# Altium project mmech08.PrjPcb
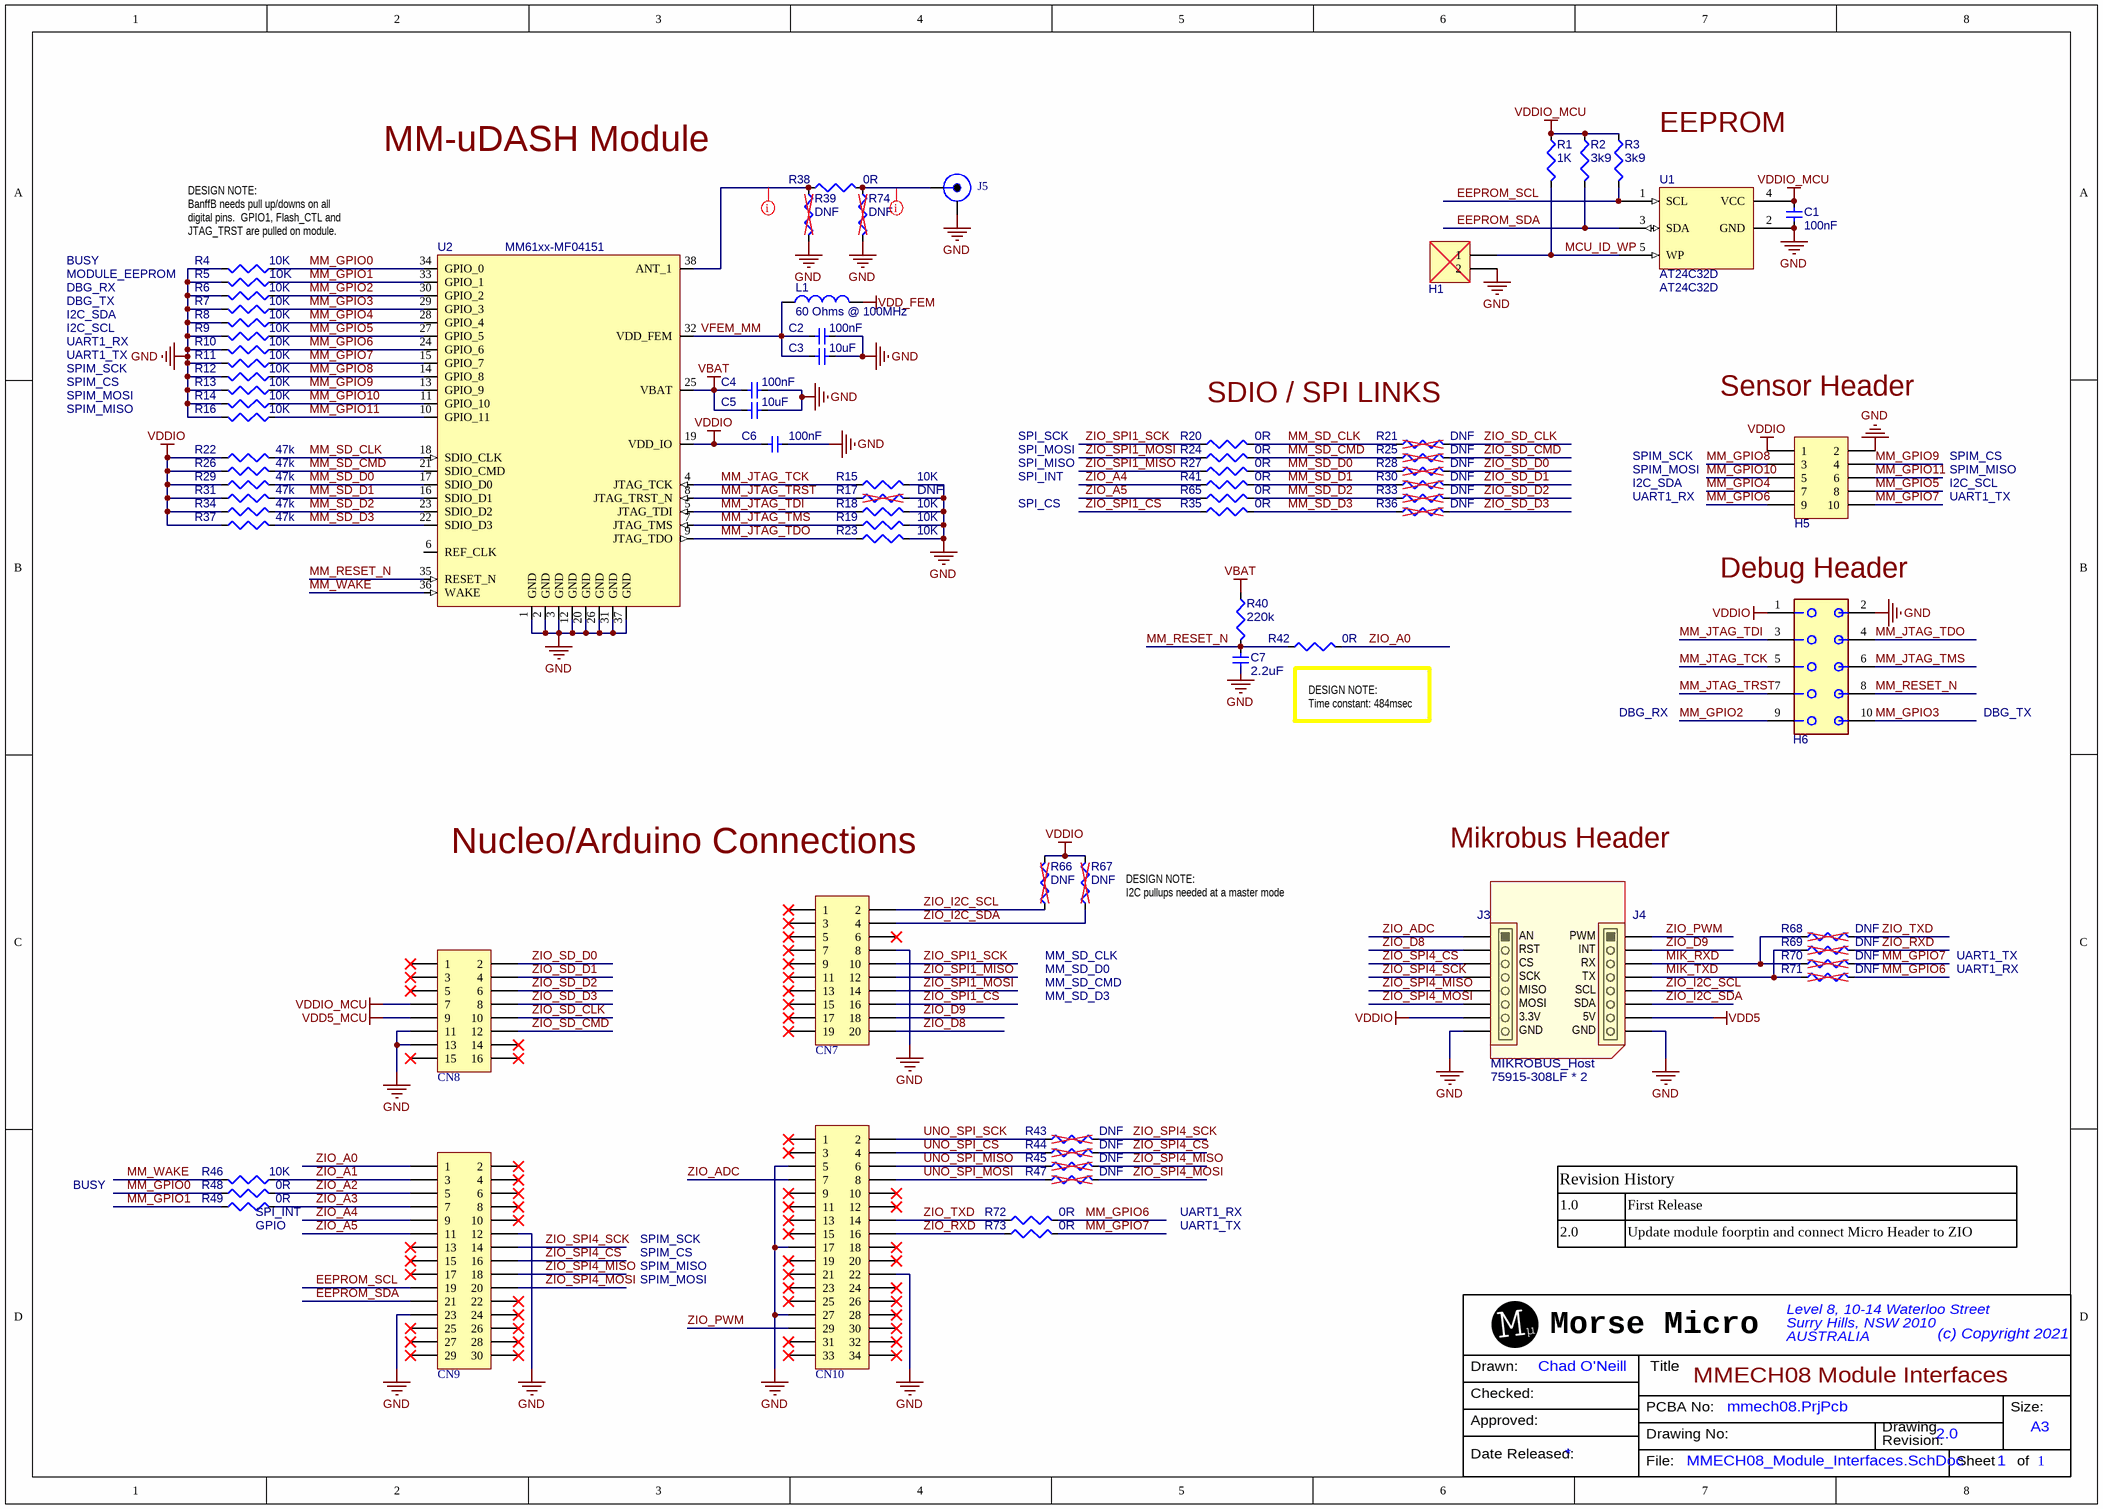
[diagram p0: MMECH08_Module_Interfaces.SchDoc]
Project: MM_EVC3; Revision: 1
2 sheets, 121 parts. Net scope: global (net labels, ports and power ports of the same name join across sheets).
Board file: mmech08.PcbDoc
Sheets:
  MMECH08_Module_Interfaces.SchDoc
  MMECH08_Power.SchDoc

## Sheet MMECH08_Module_Interfaces.SchDoc: MMECH08 Module Interfaces
size A3; Organization: Morse Micro; Revision: 2.0; SheetNumber: 1; SheetTotal: 1; DrawnBy: Chad O'Neill; Engineer: Insu Moon

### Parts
C1  value 100nF  [0402_cap]  (hidden comment: CAP)
C2  value 100nF  [0402_cap]  (hidden comment: CAP)
C3  value 10uF  [0402_cap]  (hidden comment: CAP)
C4  value 100nF  [0402_cap]  (hidden comment: CAP)
C5  value 10uF  [0402_cap]  (hidden comment: CAP)
C6  value 100nF  [0402_cap]  (hidden comment: CAP)
C7  value 2.2uF  [0402_cap]  (hidden comment: CAP)
CN7  .Designator  [HDR2X10]  (value not drawn)
CN8  .Designator  [HDR2X8]  (value not drawn)
CN9  .Designator  [HDR2X15]  (value not drawn)
CN10  .Designator  [HDR2X17]  (value not drawn)
H1  HDR_1X2_DNF  [HDR1X2_DNF]  (value not drawn)  (no BOM)
H5  HDR_2X5  [HDR2X5]  (value not drawn)
H6  2X5_FTSH_DV_K  [FTSH_105_D_K]  (value not drawn)
J3  75915-308LF * 2  [75915-308LF]
J4  75915-308LF  [75915-308LF]  (value not drawn)
J5  SMA-EDGE  [SMA_RA-Edge]  (value not drawn)
L1  value 60 Ohms @ 100MHz  [0402_ind]  (hidden comment: IND)
R1  value 1K  [0402_res]  (hidden comment: RES)
R2  value 3k9  [0402_res]  (hidden comment: RES)
R3  value 3k9  [0402_res]  (hidden comment: RES)
R4  value 10K  [0402_res]  (hidden comment: RES)
R5  value 10K  [0402_res]  (hidden comment: RES)
R6  value 10K  [0402_res]  (hidden comment: RES)
R7  value 10K  [0402_res]  (hidden comment: RES)
R8  value 10K  [0402_res]  (hidden comment: RES)
R9  value 10K  [0402_res]  (hidden comment: RES)
R10  value 10K  [0402_res]  (hidden comment: RES)
R11  value 10K  [0402_res]  (hidden comment: RES)
R12  value 10K  [0402_res]  (hidden comment: RES)
R13  value 10K  [0402_res]  (hidden comment: RES)
R14  value 10K  [0402_res]  (hidden comment: RES)
R15  value 10K  [0402_res]  (hidden comment: RES)
R16  value 10K  [0402_res]  (hidden comment: RES)
R17  value DNF  [0402_res_dnf]  (hidden comment: RES_DNF)  (no BOM)
R18  value 10K  [0402_res]  (hidden comment: RES)
R19  value 10K  [0402_res]  (hidden comment: RES)
R20  value 0R  [0603_res]  (hidden comment: RES)
R21  value DNF  [0603_res_dnf]  (hidden comment: RES_DNF)  (no BOM)
R22  value 47k  [0402_res]  (hidden comment: RES)
R23  value 10K  [0402_res]  (hidden comment: RES)
R24  value 0R  [0603_res]  (hidden comment: RES)
R25  value DNF  [0603_res_dnf]  (hidden comment: RES_DNF)  (no BOM)
R26  value 47k  [0402_res]  (hidden comment: RES)
R27  value 0R  [0603_res]  (hidden comment: RES)
R28  value DNF  [0603_res_dnf]  (hidden comment: RES_DNF)  (no BOM)
R29  value 47k  [0402_res]  (hidden comment: RES)
R30  value DNF  [0603_res_dnf]  (hidden comment: RES_DNF)  (no BOM)
R31  value 47k  [0402_res]  (hidden comment: RES)
R33  value DNF  [0603_res_dnf]  (hidden comment: RES_DNF)  (no BOM)
R34  value 47k  [0402_res]  (hidden comment: RES)
R35  value 0R  [0603_res]  (hidden comment: RES)
R36  value DNF  [0603_res_dnf]  (hidden comment: RES_DNF)  (no BOM)
R37  value 47k  [0402_res]  (hidden comment: RES)
R38  value 0R  [0402_res]  (hidden comment: RES)
R39  value DNF  [0402_res_dnf]  (hidden comment: RES_DNF)  (no BOM)
R40  value 220k  [0402_res]  (hidden comment: RES)
R41  value 0R  [0603_res]  (hidden comment: RES)
R42  value 0R  [0402_res]  (hidden comment: RES)
R43  value DNF  [0603_res_dnf]  (hidden comment: RES_DNF)  (no BOM)
R44  value DNF  [0603_res_dnf]  (hidden comment: RES_DNF)  (no BOM)
R45  value DNF  [0603_res_dnf]  (hidden comment: RES_DNF)  (no BOM)
R46  value 10K  [0402_res]  (hidden comment: RES)
R47  value DNF  [0603_res_dnf]  (hidden comment: RES_DNF)  (no BOM)
R48  value 0R  [0402_res]  (hidden comment: RES)
R49  value 0R  [0402_res]  (hidden comment: RES)
R65  value 0R  [0603_res]  (hidden comment: RES)
R66  value DNF  [0603_res_dnf]  (hidden comment: RES_DNF)  (no BOM)
R67  value DNF  [0603_res_dnf]  (hidden comment: RES_DNF)  (no BOM)
R68  value DNF  [0603_res_dnf]  (hidden comment: RES_DNF)  (no BOM)
R69  value DNF  [0603_res_dnf]  (hidden comment: RES_DNF)  (no BOM)
R70  value DNF  [0603_res_dnf]  (hidden comment: RES_DNF)  (no BOM)
R71  value DNF  [0603_res_dnf]  (hidden comment: RES_DNF)  (no BOM)
R72  value 0R  [0603_res]  (hidden comment: RES)
R73  value 0R  [0603_res]  (hidden comment: RES)
R74  value DNF  [0402_res_dnf]  (hidden comment: RES_DNF)  (no BOM)
U1  AT24C32D  [SOT-23_5]
U2  MM61xx-MF04151  [MF04]
U3  MIKROBUS_Host  [MIKROBUS_Host_SD]

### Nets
GND: C1.2 C2.2 C3.2 C4.1 C5.2 C6.2 C7.2 CN7.8 CN8.11 CN8.13 CN9.12 CN9.23 CN10.5 CN10.17 CN10.22 CN10.27 H1.2 H5.2 H6.2 J3.8 J4.8 J5.2 R4.2 R5.2 R6.2 R7.2 R8.2 R9.2 R10.2 R11.2 R12.2 R13.2 R14.2 R15.2 R16.2 R17.2 R18.2 R19.2 R23.2 R39.2 R74.2 U1.2(GND) U2.1(GND) U2.2(GND) U2.3(GND) U2.12(GND) U2.20(GND) U2.26(GND) U2.31(GND) U2.37(GND)
VBAT: C4.2 C5.1 R40.1 U2.25(VBAT)
VDD5: J4.7
VDD5_MCU: CN8.9
VDD_FEM: L1.2
VDDIO: C6.1 H5.1 H6.1 J3.7 R22.1 R26.1 R29.2 R31.2 R34.2 R37.1 R66.1 R67.1 U2.19(VDD_IO)
VDDIO_MCU: C1.1 CN8.7 R1.1 R2.1 R3.1 U1.4(VCC)
EEPROM_SCL: CN9.19 R3.2 U1.1(SCL)
EEPROM_SDA: CN9.21 R2.2 U1.3(SDA)
MCU_ID_WP: H1.1 R1.2 U1.5(WP)
MIK_RXD: J4.3 R68.1 R70.1
MIK_TXD: J4.4 R69.1 R71.1
MM_GPIO0: R4.1 R48.1 U2.34(GPIO_0)
MM_GPIO1: R5.1 R49.1 U2.33(GPIO_1)
MM_GPIO2: H6.9 R6.1 U2.30(GPIO_2)
MM_GPIO3: H6.10 R7.1 U2.29(GPIO_3)
MM_GPIO4: H5.7 R8.1 U2.28(GPIO_4)
MM_GPIO5: H5.8 R9.1 U2.27(GPIO_5)
MM_GPIO6: H5.9 R10.1 R71.2 R72.2 U2.24(GPIO_6)
MM_GPIO7: H5.10 R11.1 R70.2 R73.2 U2.15(GPIO_7)
MM_GPIO8: H5.3 R12.1 U2.14(GPIO_8)
MM_GPIO9: H5.4 R13.1 U2.13(GPIO_9)
MM_GPIO10: H5.5 R14.1 U2.11(GPIO_10)
MM_GPIO11: H5.6 R16.1 U2.10(GPIO_11)
MM_JTAG_TCK: H6.5 R15.1 U2.4(JTAG_TCK)
MM_JTAG_TDI: H6.3 R18.1 U2.5(JTAG_TDI)
MM_JTAG_TDO: H6.4 R23.1 U2.9(JTAG_TDO)
MM_JTAG_TMS: H6.6 R19.1 U2.7(JTAG_TMS)
MM_JTAG_TRST: H6.7 R17.1 U2.8(JTAG_TRST_N)
MM_RESET_N: C7.1 H6.8 R40.2 R42.1 U2.35(RESET_N)
MM_SD_CLK: R20.2 R21.1 R22.2 U2.18(SDIO_CLK)
MM_SD_CMD: R24.2 R25.1 R26.2 U2.21(SDIO_CMD)
MM_SD_D0: R27.2 R28.1 R29.1 U2.17(SDIO_D0)
MM_SD_D1: R30.1 R31.1 R41.2 U2.16(SDIO_D1)
MM_SD_D2: R33.1 R34.1 R65.2 U2.23(SDIO_D2)
MM_SD_D3: R35.2 R36.1 R37.2 U2.22(SDIO_D3)
MM_WAKE: R46.1 U2.36(WAKE)
UNO_SPI_CS: CN10.4 R44.1
UNO_SPI_MISO: CN10.6 R45.1
UNO_SPI_MOSI: CN10.8 R47.1
UNO_SPI_SCK: CN10.2 R43.1
VFEM_MM: C2.1 C3.1 L1.1 U2.32(VDD_FEM)
ZIO_A0: CN9.1 R42.2
ZIO_A1: CN9.3 R46.2
ZIO_A2: CN9.5 R48.2
ZIO_A3: CN9.7 R49.2
ZIO_A4: CN9.9 R41.1
ZIO_A5: CN9.11 R65.1
ZIO_ADC: CN10.7 J3.1
ZIO_D8: CN7.20 J3.2
ZIO_D9: CN7.18 J4.2
ZIO_I2C_SCL: CN7.2 J4.5 R66.2
ZIO_I2C_SDA: CN7.4 J4.6 R67.2
ZIO_PWM: CN10.29 J4.1
ZIO_RXD: CN10.16 R69.2 R73.1
ZIO_SD_CLK: CN8.10 R21.2
ZIO_SD_CMD: CN8.12 R25.2
ZIO_SD_D0: CN8.2 R28.2
ZIO_SD_D1: CN8.4 R30.2
ZIO_SD_D2: CN8.6 R33.2
ZIO_SD_D3: CN8.8 R36.2
ZIO_SPI1_CS: CN7.16 R35.1
ZIO_SPI1_MISO: CN7.12 R27.1
ZIO_SPI1_MOSI: CN7.14 R24.1
ZIO_SPI1_SCK: CN7.10 R20.1
ZIO_SPI4_CS: CN9.16 J3.3 R44.2
ZIO_SPI4_MISO: CN9.18 J3.5 R45.2
ZIO_SPI4_MOSI: CN9.20 J3.6 R47.2
ZIO_SPI4_SCK: CN9.14 J3.4 R43.2
ZIO_TXD: CN10.14 R68.2 R72.1
NetJ5_1: J5.1 R38.2 R74.1
NetR38_1: R38.1 R39.1 U2.38(ANT_1)

Not connected (* = marked no-connect by the designer): CN7 1* 3* 5* 6* 7* 9* 11* 13* 15* 17* 19*; CN8 1* 3* 5* 14* 15* 16*; CN9 2* 4* 6* 8* 10* 13* 15* 17* 22* 24* 25* 26* 27* 28* 29* 30*; CN10 1* 3* 9* 10* 11* 12* 13* 15* 18* 19* 20* 21* 23* 24* 25* 26* 28* 30* 31* 32* 33* 34*; U2 6(REF_CLK)

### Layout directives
net class RF-Net: NetJ5_1, NetR38_1

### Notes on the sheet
- MM-uDASH Module
- EEPROM
- DESIGN NOTE:
  BanffB needs pull up/downs on all digital pins.  GPIO1, Flash_CTL and JTAG_TRST are pulled on module.
- DBG_RX
- DBG_TX
- BUSY
- I2C_SDA
- MODULE_EEPROM
- SPIM_SCK
- I2C_SCL
- UART1_RX
- UART1_TX
- SPIM_CS
- SPIM_MOSI
- SPIM_MISO
- SPI_MOSI
- SPI_SCK
- SDIO / SPI LINKS
- (near H5) Sensor Header
- SPI_MISO
- SPI_CS
- SPI_INT
- (near H6) Debug Header
- (near R42) DESIGN NOTE:
  Time constant: 484msec
- (near CN7) Nucleo/Arduino Connections
- Mikrobus Header
- (near R67) DESIGN NOTE:
  I2C pullups needed at a master mode
- MM_SD_CLK
- MM_SD_D0
- MM_SD_CMD
- MM_SD_D3
- Revision History
- (near R49) SPI_INT
- (near R49) GPIO
- 1.0
- 2.0
- First Release
- Update module foorptin and connect Micro Header to ZIO

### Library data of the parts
C1 C2 C4 C6 = CAP0084: Cap,100nF,10V,+/-10%,X7R,0402; Manufacturer 1: Kemet; Manufacturer Part Number 1: C0402C104K8RACTU; Generic Allowed: Yes; Subtype: Ceramic; Tolerance: 10%
C3 C5 = CAP0014: CAP CER 10UF 10V 20% X5R 0402; Manufacturer 1: Samsung; Manufacturer Part Number 1: CL05A106MP8NUB8; Generic Allowed: Yes; Subtype: Ceramic
C7 = CAP0023: CAP CER 2.2UF 25V 20% X5R 0402; Manufacturer 1: Murata; Manufacturer Part Number 1: GRM155R61E225ME15D; Generic Allowed: Yes; Subtype: Ceramic
CN7 = HDR0019: Conn Straight Header 10x2 0.100" 20 POS; Manufacturer 1: Molex/Waldom Electronics Corp; Manufacturer Part Number 1: 90131-0130; Generic Allowed: Yes
CN8 = HDR0015: Conn Straight Header 8x2 0.100" 16 POS; Manufacturer 1: Molex/Waldom Electronics Corp; Manufacturer Part Number 1: 90131-0128; Generic Allowed: Yes
CN9 = HDR0027: Conn Straight Header 15x2 0.100" 30 POS; Manufacturer 1: Molex/Waldom Electronics Corp; Manufacturer Part Number 1: 90131-0135; Generic Allowed: Yes
CN10 = HDR0029: Conn Straight Header 17x2 0.100" 32 POS; Manufacturer 1: Molex/Waldom Electronics Corp; Manufacturer Part Number 1: 90131-0137; Generic Allowed: Yes
H1 = HDR0098: Conn Straight Header 2x1 0.100" 2 POS (DNF)
H5 = HDR0012: Conn Straight Header 5x2 0.100" 10 POS; Manufacturer 1: Molex/Waldom Electronics Corp; Manufacturer Part Number 1: 90131-0125; Generic Allowed: Yes
H6 = HDR0090: CONN,Vertical FTSH Series,0.05"10 Pins, Through Hole; Manufacturer 1: Samtec; Manufacturer Part Number 1: FTSH-105-01-F-D-K; Generic Allowed: No
J3 J4 = CON0063: CONN RCPT 8POS 0.1 GOLD PCB; Manufacturer 1: Amphenol FCI; Generic Allowed: No
J5 = CON0004: Conn SMA Right Angel .187" Female Socket; Manufacturer 1: Emerson Network; Manufacturer Part Number 1: 142-0701-801; Rule: UNIONINDEX{}0[]RULEKIND{}PolygonConnect[]NETSCOPE{}DifferentNets[]LAYERKIND{}SameLayer[]NAME{}Schematic Polygon Connect Style[]CONNECTSTYLE{}Direct[]RELIEFCONDUCTORWIDTH{}10mil[]RELIEFENTRIES{}4[]POLYGONRELIEFANGLE{}45 Angle[]UNIT{}Imperial[]PcbType{}ProtelPcb; Generic Allowed: No
L1 = IND0083: BEAD 60OHMS 2500MA 32 MOHM; Manufacturer 1: Murata; Manufacturer Part Number 1: BLM15PX600SN1D; Current: 2.5A; Generic Allowed: Yes; Resistance: 32mOhm
R1 = RES0004: RES SMD 1Kohm 1% 1/10W Thick film 0402; Manufacturer 1: Panasonic; Manufacturer Part Number 1: ERJ-2RKF1001X; Generic Allowed: Yes
R2 R3 = RES0204: RES SMD 3.9K OHM 1% 1/16W 0402; Manufacturer 1: Yageo; Manufacturer Part Number 1: RC0402FR-073K9L; Generic Allowed: Yes
R4-R16 R18 R19 R23 R46 = RES0002: RES SMD 10Kohm 1% 1/10W Thick film 0402; Manufacturer 1: Panasonic; Manufacturer Part Number 1: ERJ-2RKF1002X; Generic Allowed: Yes
R17 R39 R74 = RES0034: Update Later
R20 R24 R27 R35 R41 R65 R72 R73 = RES0119: Res, 0 Ohm, 1/10W,+/-5%,0603 RoHS; Manufacturer 1: Rohm; Manufacturer Part Number 1: MCR03EZPJ000; Tolerance: 5%; Generic Allowed: Yes
R21 R25 R28 R30 R33 R36 R43-R45 R47 R66-R71 = RES0035: Update Later
R22 R26 R29 R31 R34 R37 = RES0086: Res, 47K Ohms,1/16W, 1%, 0402,SMD RoHS; Manufacturer 1: Rohm; Manufacturer Part Number 1: MCR01MZPF4702; Generic Allowed: Yes
R38 R42 R48 R49 = RES0001: RES SMD 0ohm 1% 1/10W Thick film 0402; Manufacturer 1: Panasonic; Manufacturer Part Number 1: ERJ-2GE0R00X; Generic Allowed: Yes
R40 = RES0064: Res, 220k Ohms, 1/16W, 1%, 0402,SMD; Manufacturer 1: Rohm; Manufacturer Part Number 1: MCR01MZPF2203; Generic Allowed: Yes
U1 = ICT0181: IC EEPROM 32KBIT I2C SOT23-5; Manufacturer 1: Microchip Technology; Manufacturer Part Number 1: AT24C32D-STUM-T; Generic Allowed: No
U2 = MOD0007: MM61xx-MF04; Manufacturer 1: Morse Micro
U3 = MOD0012: MIKROBUS Module; Manufacturer Part Number 1: MIKROBUS HOST; Value: MIKROBUS Host

## Sheet MMECH08_Power.SchDoc: MMECH08 Power & Reset
size A3; CompanyName: Morse Micro; DrawnBy: Insu Moon; Engineer: Insu Moon; Revision: 1.0; SheetNumber: 2; SheetTotal: 2; pageName: Regulators; DrawingNumber: 1; PageSetup: Record=PageOptions¦CenterHorizontal=True¦CenterVertical=True¦PrintScale=1.04¦XCorrection=1.00¦YCorrection=1.00¦PrintKind=0¦BorderSize=5000000¦LeftOffset=0¦BottomOffset=0¦Orientation=2¦PaperLength=1000¦PaperWidth=1000¦Scale=100¦PaperSource=7¦PrintQuality=-4¦MediaType=1¦DitherType=10¦PaperKind=A3¦PrintScaleMode=1
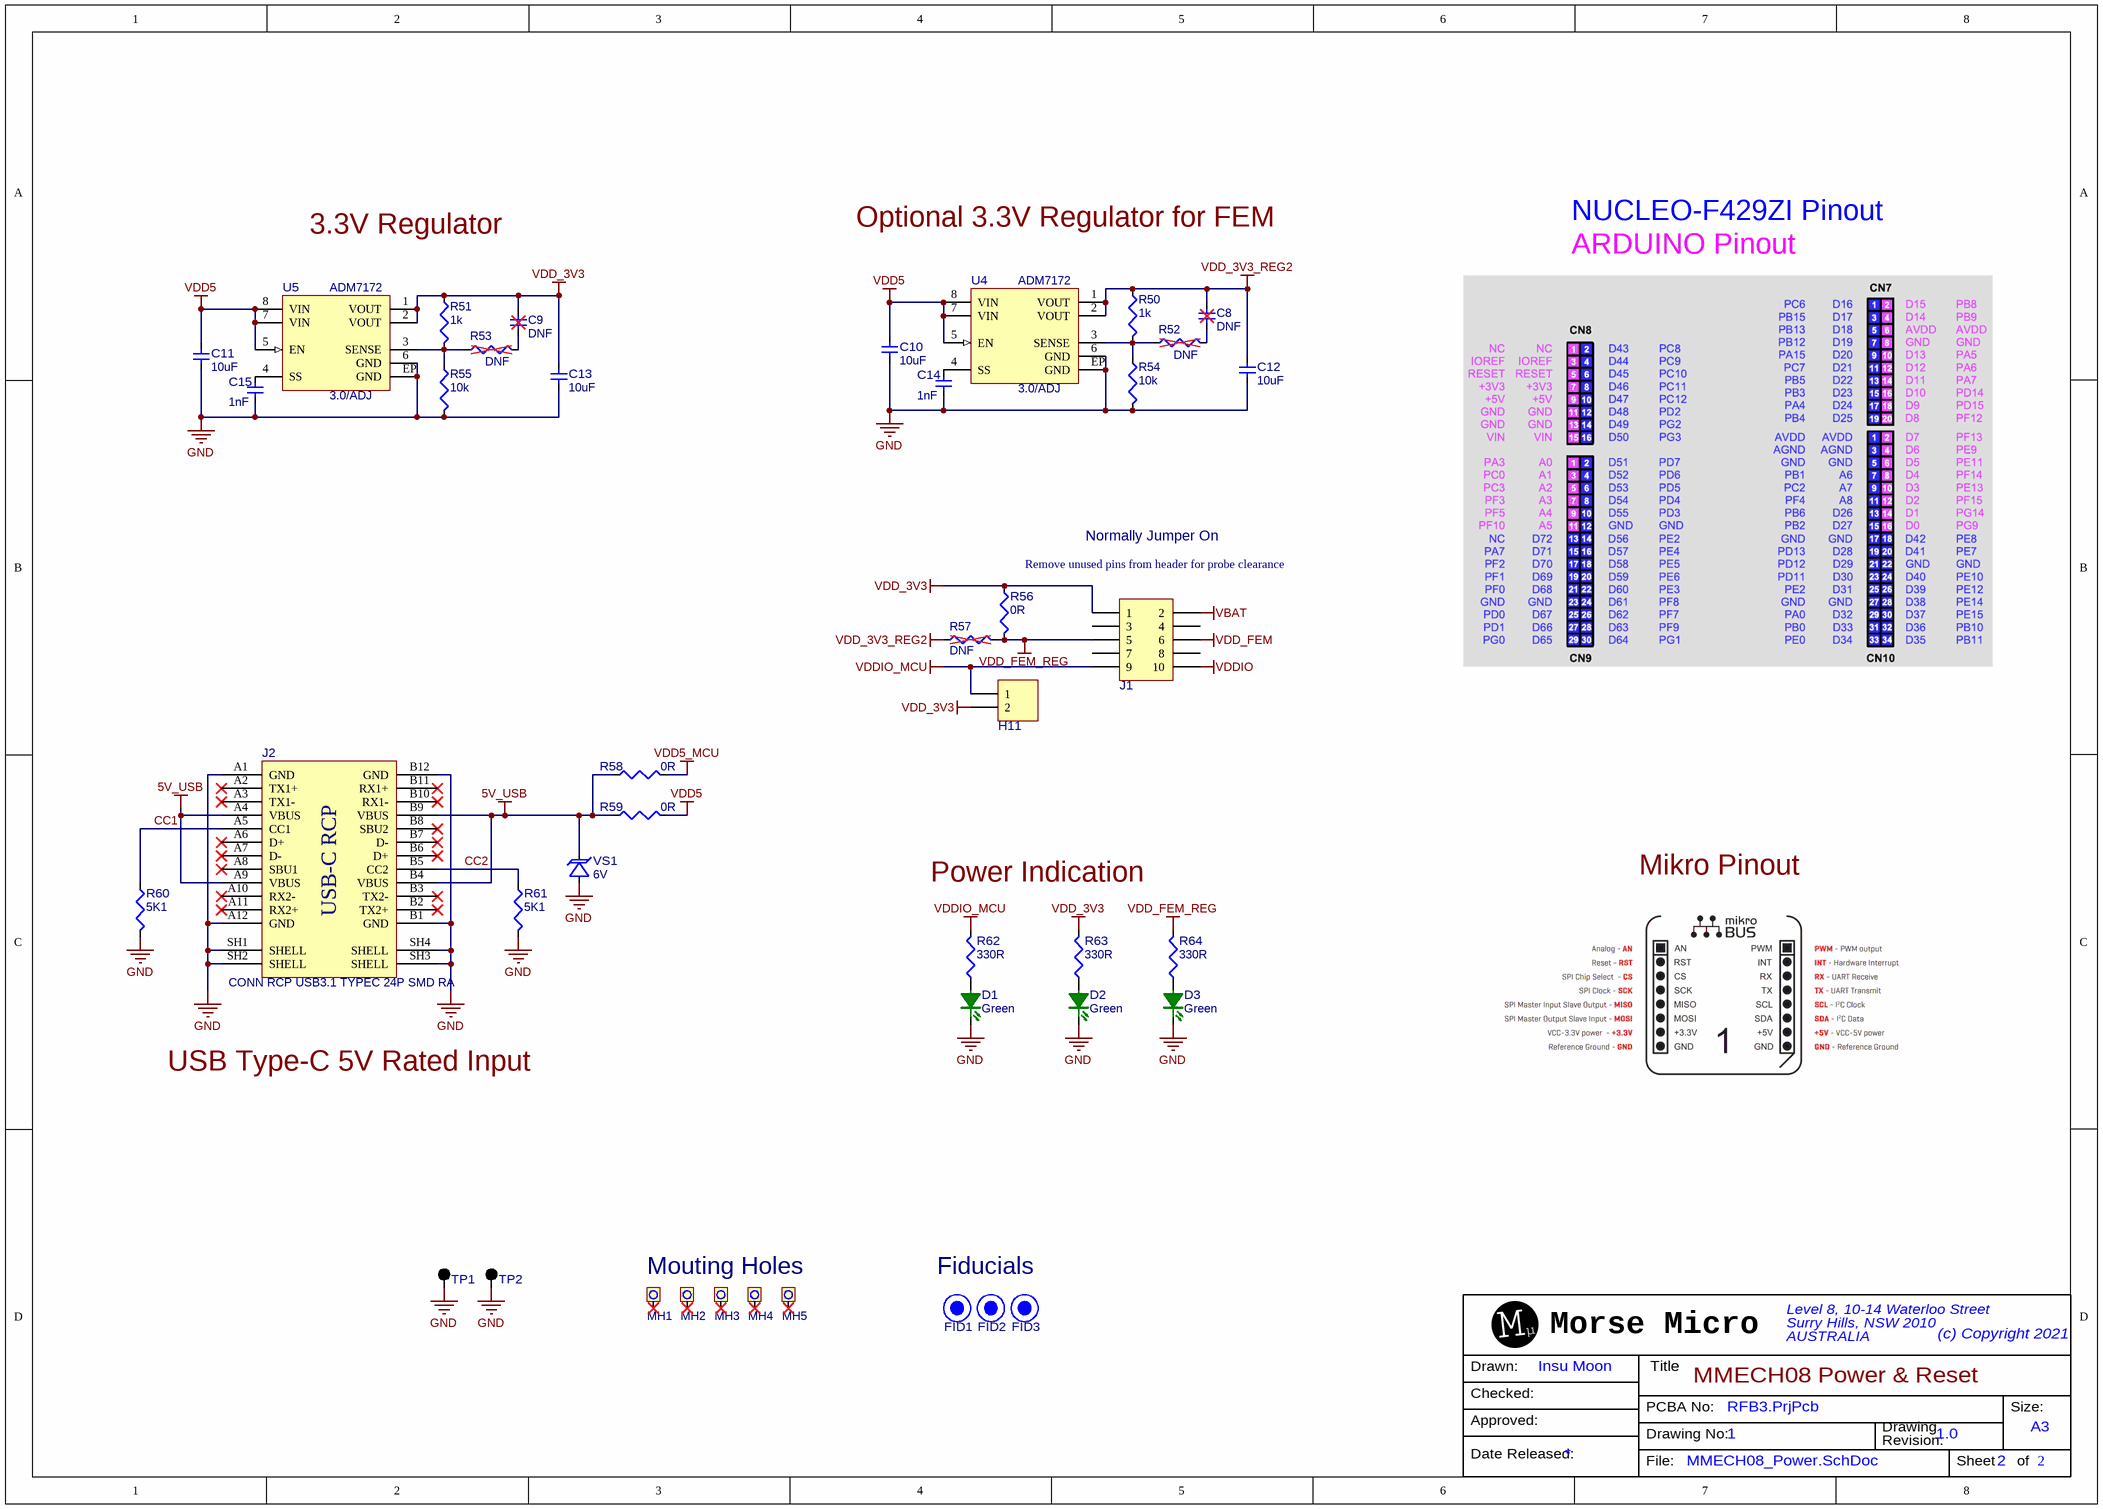
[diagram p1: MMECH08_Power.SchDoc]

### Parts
C8  value DNF  [0402_cap_dnf]  (hidden comment: CAP_DNF)  (no BOM)
C9  value DNF  [0402_cap_dnf]  (hidden comment: CAP_DNF)  (no BOM)
C10  value 10uF  [0603_cap]  (hidden comment: CAP)
C11  value 10uF  [0603_cap]  (hidden comment: CAP)
C12  value 10uF  [0603_cap]  (hidden comment: CAP)
C13  value 10uF  [0603_cap]  (hidden comment: CAP)
C14  value 1nF  [0402_cap]  (hidden comment: CAP)
C15  value 1nF  [0402_cap]  (hidden comment: CAP)
D1  value Green  [LED_0402_GREEN]  (hidden comment: LED_G)
D2  value Green  [LED_0402_GREEN]  (hidden comment: LED_G)
D3  value Green  [LED_0402_GREEN]  (hidden comment: LED_G)
FID1  FIDUCIAL  [FIDUCIAL_1MM]  (value not drawn)  (no BOM)
FID2  FIDUCIAL  [FIDUCIAL_1MM]  (value not drawn)  (no BOM)
FID3  FIDUCIAL  [FIDUCIAL_1MM]  (value not drawn)  (no BOM)
H11  HDR_1X2  [HDR1X2]  (value not drawn)
J1  HDR_2X5  [HDR2X5]  (value not drawn)
J2  CONN RCP USB3.1 TYPEC 24P SMD RA  [USB-C_RCP]
MH1  MH_360_320_NPTH  [MH_360_320_NPTH]  (value not drawn)
MH2  MH_360_320_NPTH  [MH_360_320_NPTH]  (value not drawn)
MH3  MH_360_320_NPTH  [MH_360_320_NPTH]  (value not drawn)
MH4  MH_360_320_NPTH  [MH_360_320_NPTH]  (value not drawn)
MH5  MH_360_320_NPTH  [MH_360_320_NPTH]  (value not drawn)
R50  value 1k  [0402_res]  (hidden comment: RES)
R51  value 1k  [0402_res]  (hidden comment: RES)
R52  value DNF  [0402_res_dnf]  (hidden comment: RES_DNF)  (no BOM)
R53  value DNF  [0402_res_dnf]  (hidden comment: RES_DNF)  (no BOM)
R54  value 10k  [0402_res]  (hidden comment: RES)
R55  value 10k  [0402_res]  (hidden comment: RES)
R56  value 0R  [0603_res]  (hidden comment: RES)
R57  value DNF  [0603_res_dnf]  (hidden comment: RES_DNF)  (no BOM)
R58  value 0R  [0603_res]  (hidden comment: RES)
R59  value 0R  [0603_res]  (hidden comment: RES)
R60  value 5K1  [0402_res]  (hidden comment: RES)
R61  value 5K1  [0402_res]  (hidden comment: RES)
R62  value 330R  [0402_res]  (hidden comment: RES)
R63  value 330R  [0402_res]  (hidden comment: RES)
R64  value 330R  [0402_res]  (hidden comment: RES)
TP1  TP-BLK  [TP-100_BLACK]  (value not drawn)
TP2  TP-BLK  [TP-100_BLACK]  (value not drawn)
U4  Voltage: 3.0/ADJ  [PSON50P300X80_HS-9N]  (hidden comment: ADM7172)
U5  Voltage: 3.0/ADJ  [PSON50P300X80_HS-9N]  (hidden comment: ADM7172)
VS1  value 6V  [DO-214AC]  (hidden comment: Varistor_Uni)

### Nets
5V_USB: J2.A4(VBUS) J2.A9(VBUS) J2.B4(VBUS) J2.B9(VBUS) R58.1 R59.1 VS1.K
GND: C10.2 C11.2 C12.2 C13.2 C14.2 C15.2 D1.K D2.K D3.K J2.A1(GND) J2.A12(GND) J2.B1(GND) J2.B12(GND) J2.SH1(SHELL) J2.SH2(SHELL) J2.SH3(SHELL) J2.SH4(SHELL) R54.2 R55.2 R60.2 R61.2 TP1.1 TP2.1 U4.6(GND) U4.EP(GND) U5.6(GND) U5.EP(GND) VS1.A
VBAT: J1.2
VDD5: C10.1 C11.1 R59.2 U4.5(EN) U4.7(VIN) U4.8(VIN) U5.5(EN) U5.7(VIN) U5.8(VIN)
VDD5_MCU: R58.2
VDD_3V3: C9.1 C13.1 H11.2 J1.1 R51.1 R56.1 R63.2 U5.1(VOUT) U5.2(VOUT)
VDD_3V3_REG2: C8.1 C12.1 R50.1 R57.1 U4.1(VOUT) U4.2(VOUT)
VDD_FEM: J1.6
VDD_FEM_REG: J1.5 R56.2 R57.2 R64.2
VDDIO: J1.10
VDDIO_MCU: H11.1 J1.9 R62.2
CC1: J2.A5(CC1) R60.1
CC2: J2.B5(CC2) R61.1
NetC8_2: C8.2 R52.2
NetC9_2: C9.2 R53.2
NetC14_1: C14.1 U4.4(SS)
NetC15_1: C15.1 U5.4(SS)
NetD1_A: D1.A R62.1
NetD2_A: D2.A R63.1
NetD3_A: D3.A R64.1
NetR50_2: R50.2 R52.1 R54.1 U4.3(SENSE)
NetR51_2: R51.2 R53.1 R55.1 U5.3(SENSE)

Not connected (* = marked no-connect by the designer): J1 3 4 7 8; J2 A2(TX1+)* A3(TX1-)* A6(D+)* A7(D-)* A8(SBU1)* A10(RX2-)* A11(RX2+)* B2(TX2+)* B3(TX2-)* B6(D+)* B7(D-)* B8(SBU2)* B10(RX1-)* B11(RX1+)*; MH1 1*; MH2 1*; MH3 1*; MH4 1*; MH5 1*

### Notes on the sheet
- 3.3V Regulator
- Optional 3.3V Regulator for FEM
- NUCLEO-F429ZI Pinout
- ARDUINO Pinout
- Remove unused pins from header for probe clearance
- Normally Jumper On
- Power Indication
- Mikro Pinout
- USB Type-C 5V Rated Input
- Mouting Holes
- Fiducials

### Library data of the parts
C8 C9 = CAP0049: Update Later
C10-C13 = CAP0164: CAP CER 10UF 25V 20% X5R 0603; Manufacturer 1: Murata, Inc.; Manufacturer Part Number 1: GRM188R61E106MA73J; Generic Allowed: Yes; Subtype: Ceramic
C14 C15 = CAP0078: Cap,1nF,50V,+/-10%,X7R,0402, RoHS; Manufacturer 1: Murata, Inc.; Manufacturer Part Number 1: GRM155R71H102KA01D; Generic Allowed: Yes; Subtype: Ceramic; Tolerance: 10%
D1-D3 = DIO0046: LED GREEN 0402 SMD; Manufacturer 1: SunLED; Manufacturer Part Number 1: XZVGR68W-3; Generic Allowed: Yes; Voltage: 2.0V
FID1-FID3 = PAD0013: 1mm Round Fiducial, 0.5mm Space; Rule: UNIONINDEX{}0[]RULEKIND{}Clearance[]NETSCOPE{}AnyNet[]LAYERKIND{}SameLayer[]NAME{}Schematic Clearance Constraint[]GAP{}0mil[]UNIT{}Imperial[]PcbType{}ProtelPcb
H11 = HDR0006: Conn Straight Header 2x1 0.100" 2 POS; Manufacturer 1: Oupiin; Manufacturer Part Number 1: 2011-1X02G00SB-1; Generic Allowed: Yes
J1 = HDR0012: as H5 on sheet MMECH08_Module_Interfaces
J2 = CON0045: Manufacturer 1: Molex; Generic Allowed: Yes
MH1-MH5 = PAD0034: MH NPTH 3.60mm DIA 3.20mm HOLE
R50 R51 = RES0042: Res, 1k Ohms, 1/16W, 1%, 0402,SMD; Manufacturer 1: Yageo; Manufacturer Part Number 1: RC0402FR-071KL; Generic Allowed: Yes
R52 R53 = RES0034: Update Later
R54 R55 = RES0043: Res,10K Ohms,1/16W, 1%, 0402,SMD RoHS; Manufacturer 1: Rohm; Manufacturer Part Number 1: MCR01MZPF1002; Generic Allowed: Yes
R56 = RES0119: as R20 on sheet MMECH08_Module_Interfaces
R57 = RES0035: Update Later
R58 R59 = RES0119: Res, 0 Ohm, 1/10W,+/-5%,0603 RoHS; Manufacturer 1: Rohm; Manufacturer Part Number 1: MCR03EZPJ000; Generic Allowed: Yes; Tolerance: 5%
R60 R61 = RES0094: Res, 5.1K Ohms, 1/16W, 1%, 0402,SMD; Manufacturer 1: Rohm; Manufacturer Part Number 1: MCR01MZPF5101; Generic Allowed: Yes
R62-R64 = RES0073: Res, 330 Ohms, 1/16W, 1%, 0402,SMD; Manufacturer 1: Rohm; Manufacturer Part Number 1: MCR01MZPF3300; Generic Allowed: Yes
TP1 TP2 = CON0001: Test Point PCB, BLACK 0.040"D; Manufacturer 1: Keystone Electronics; Manufacturer Part Number 1: 5001; Generic Allowed: Yes
U4 U5 = REG0068: IC REG LINEAR POS 3.0 2A 8LFCSP; Manufacturer 1: Analog Devices Inc.; Manufacturer Part Number 1: ADM7172ACPZ-3.0-R7; Generic Allowed: No
VS1 = DIO0056: TVS DIODE 6V 10.3V DO214AC; Manufacturer 1: Littelfuse Inc.; Manufacturer Part Number 1: SMAJ6.0A; Current: 38.8A; Generic Allowed: Yes

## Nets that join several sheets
GND: MMECH08_Module_Interfaces (50 pins), MMECH08_Power (28 pins)
VBAT: MMECH08_Module_Interfaces (C4.2 C5.1 R40.1 U2.25), MMECH08_Power (J1.2)
VDD5: MMECH08_Module_Interfaces (J4.7), MMECH08_Power (9 pins)
VDD5_MCU: MMECH08_Module_Interfaces (CN8.9), MMECH08_Power (R58.2)
VDD_FEM: MMECH08_Module_Interfaces (L1.2), MMECH08_Power (J1.6)
VDDIO: MMECH08_Module_Interfaces (13 pins), MMECH08_Power (J1.10)
VDDIO_MCU: MMECH08_Module_Interfaces (6 pins), MMECH08_Power (H11.1 J1.9 R62.2)

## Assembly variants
Default Build: not fitted C8 C8 C10 C12 C14 R21 R25 R28 R30 R31 R32 R33 R36 R50 R51 R52 R53 R54 R58 R58 R59 R60 R61 R66 R67 R? R? R? R? U3 U4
